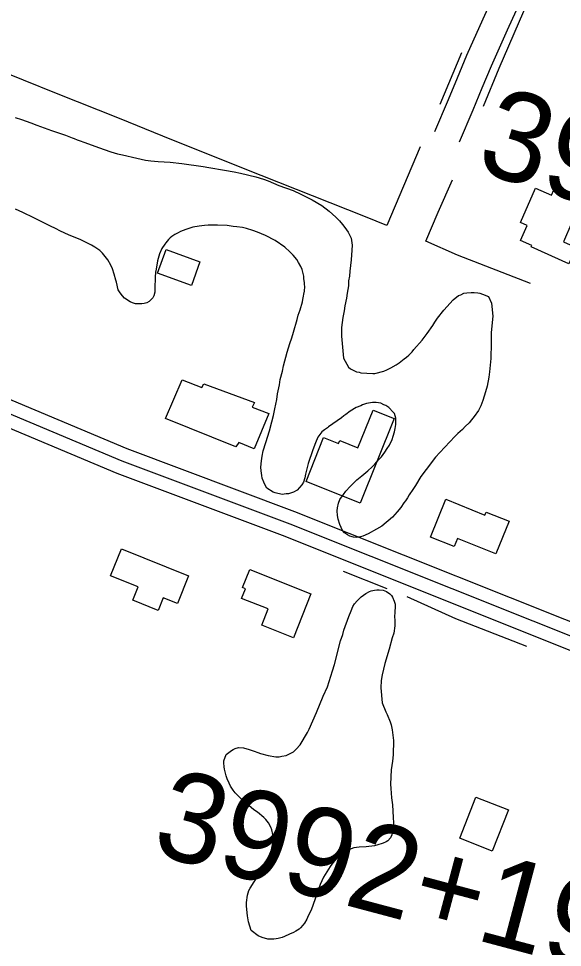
# Model space of a CAD drawing. Extents: x 3297735 to 3335592, y 670436 to 695807.
# Drawn here: x 3315202 to 3315811, y 691960 to 693000 of the extents above; entities that cross this region are included whole.
import ezdxf

# ---------------------------------------------------------------- set-up
doc = ezdxf.new("R2010")
doc.units = 0
for name, color, linetype in [('V-BLDG-OTLN', 7, 'Continuous'), ('V-BORW-LINE', 7, 'Continuous'), ('V-ROAD-CNTR', 7, 'Continuous'), ('V-SITE-VEGE', 7, 'Continuous'), ('V-SURV-IDEN', 7, 'Continuous'), ('V-TOPO-SHOR', 7, 'Continuous')]:
    doc.layers.add(name, color=color, linetype=linetype)

msp = doc.modelspace()

# ---------------------------------------------------------------- linework, layer by layer
at = {"layer": 'V-BLDG-OTLN'}
for points in [[(3315801.5, 692808), (3315857, 692783.3), (3315846.9, 692760.3), (3315821.9, 692771.4), (3315812.3, 692749.6), (3315826.5, 692743.3), (3315818.5, 692725.3), (3315776.3, 692744), (3315777, 692745.6), (3315764.3, 692751.3), (3315771.8, 692768.2), (3315764.1, 692771.6), (3315781, 692809.8), (3315798.8, 692801.9)], [(3315367.2, 692741.2), (3315405.2, 692727.5), (3315395.6, 692700.8), (3315357.5, 692714.6)], [(3315445.2, 692520.4), (3315366.4, 692552), (3315385.3, 692595.1), (3315407.4, 692586.8), (3315409.4, 692590.9), (3315466.1, 692570), (3315463.7, 692564.5), (3315482.4, 692557.7), (3315465.9, 692518), (3315448.6, 692525.2)], [(3315622.7, 692551.9), (3315584.7, 692457), (3315524, 692481.4), (3315543.7, 692530.5), (3315560.4, 692523.8), (3315561.8, 692527.4), (3315582.2, 692519.2), (3315599.1, 692561.3)], [(3315663.5, 692419.1), (3315680.5, 692461.5), (3315724.4, 692443.9), (3315725.7, 692447.2), (3315751.4, 692436.9), (3315736.7, 692400.3), (3315693.6, 692417.5), (3315690, 692408.5)], [(3315317.3, 692406.1), (3315392.5, 692375.8), (3315380, 692344.7), (3315364, 692351.1), (3315358.3, 692337.1), (3315329.8, 692348.6), (3315335.8, 692363.4), (3315305.1, 692375.8)], [(3315461, 692382.8), (3315529.4, 692355.7), (3315510, 692306.5), (3315474.4, 692320.6), (3315481.6, 692338.7), (3315451.8, 692350.5), (3315456.1, 692361.4), (3315453, 692362.6)], [(3315696.1, 692082), (3315714.3, 692128), (3315750.7, 692113.6), (3315732.5, 692067.6)]]:
    msp.add_lwpolyline(points, close=True, dxfattribs=at)
at = {"layer": 'V-BORW-LINE'}
msp.add_spline([(3316995.2, 691930.5), (3317005, 692007.7), (3317000.7, 692060.5), (3316979, 692099.5), (3316906.2, 692141.1), (3316833.3, 692187.2), (3316697.4, 692287.6), (3316663.3, 692310.2), (3316619.6, 692296.1), (3316590.9, 692259.4), (3316565, 692210.5), (3316480.2, 692005.7), (3316389.2, 691825.2), (3316305.5, 691699.3), (3316276.5, 691659.4), (3316186.6, 691545.7), (3316036.8, 691382.1), (3315921.1, 691241.4), (3315848.1, 691140), (3315652.3, 690837.6), (3315431.2, 690420.7), (3315366.5, 690281.6), (3315351.9, 690233.4), (3315347.6, 690183.5), (3315387.2, 690117.4), (3315426.1, 690095.1), (3315473.6, 690094.3), (3315510.7, 690108.4), (3315542.5, 690128.5), (3315605.1, 690188.3), (3315659, 690264.4), (3315681, 690299), (3315904.7, 690642.2), (3316008, 690811.4), (3316078, 690936.9), (3316101.2, 690968.5), (3316112.2, 690877.5), (3316165, 690879), (3316235.5, 690925.6), (3316271.1, 690958.6), (3316327.1, 691033.6), (3316466.8, 691261.1), (3316568, 691464.7), (3316598.4, 691502.4), (3316633.6, 691520.7), (3316678.1, 691524.6), (3316723.8, 691458.6), (3316763, 691470.8), (3316787.6, 691500), (3316883.3, 691688.4), (3316909.4, 691731.2), (3316973.6, 691855.6), (3316995.2, 691930.5)], degree=3, dxfattribs=at)
at = {"layer": 'V-ROAD-CNTR'}
for points in [[(3316195.1, 692158), (3315869, 692288.8), (3315506.1, 692433.7), (3315318.1, 692504.1), (3315015.5, 692631), (3314723.7, 692747.9), (3314551, 692817.4), (3314462.7, 692856.2), (3314264.4, 692935.5), (3314179.8, 692969.1), (3313993.7, 693034.9), (3313899.6, 693073.9), (3313699.7, 693161.3), (3313629.3, 693187.1), (3313422.5, 693270.4), (3313253.4, 693339.7)], [(3316189.5, 692144.1), (3315863.5, 692274.8), (3315500.7, 692419.7), (3315312.5, 692490.2), (3315009.8, 692617.1), (3314718.1, 692734), (3314545.2, 692803.6), (3314456.9, 692842.3), (3314258.9, 692921.6), (3314174.6, 692955.1), (3313988.4, 693020.9), (3313893.7, 693060.1), (3313694.1, 693147.4), (3313623.9, 693173.1), (3313416.8, 693256.5), (3313247.7, 693325.9)], [(3315781, 693136.9), (3315740.1, 693039.1), (3315722, 692999), (3315703.8, 692958.4), (3315693.2, 692933.2), (3315683.2, 692908.7), (3315668, 692873.1)], [(3315808.1, 693123.9), (3315767.6, 693027.2), (3315749.3, 692986.7), (3315731.3, 692946.5), (3315720.9, 692921.8), (3315710.9, 692897.1), (3315695.6, 692861.3)], [(3316200.7, 692171.9), (3315874.6, 692302.7), (3315511.5, 692447.6), (3315323.6, 692518.1), (3315021.2, 692644.9), (3314797.3, 692734.6)]]:
    msp.add_lwpolyline(points, dxfattribs=at)
at = {"layer": 'V-SITE-VEGE'}
for points in [[(3315198.1, 692889.1), (3315205.1, 692886.9), (3315215.6, 692883), (3315222.3, 692880.4)], [(3315222.3, 692880.4), (3315238.8, 692874.5), (3315254.4, 692869.2), (3315262.1, 692866.3), (3315264.2, 692865.3), (3315267.6, 692864.1), (3315270, 692863.4), (3315276.2, 692861), (3315291.5, 692855.4), (3315305.4, 692850.6), (3315312.8, 692848.4), (3315318.3, 692847.2), (3315334.6, 692843.3), (3315344.2, 692841.3), (3315350, 692840.3), (3315358.3, 692839.6), (3315371.8, 692838.8), (3315385, 692837.6), (3315408.7, 692834.1), (3315415.1, 692832.9), (3315432.6, 692830), (3315443.4, 692828), (3315450.6, 692826.6), (3315467.6, 692822.7), (3315476.2, 692820), (3315481.7, 692818.1), (3315493.7, 692813), (3315509.5, 692807.2), (3315518.1, 692803.3), (3315523.4, 692800.6), (3315530.8, 692796.8), (3315541.6, 692790.5), (3315549.9, 692784.2), (3315557.4, 692777.5), (3315561.4, 692773.4), (3315565, 692769.1), (3315567.4, 692766), (3315571.2, 692760.7), (3315574.5, 692754), (3315575.7, 692746), (3315575.4, 692740.5), (3315574.7, 692729.5), (3315573, 692716.8), (3315572.5, 692711.5), (3315571.7, 692706), (3315571.5, 692700.5), (3315570.2, 692692.4), (3315569.3, 692686.6), (3315567.5, 692678.2), (3315566.8, 692672.7), (3315565.1, 692665), (3315563.6, 692653.8), (3315563.8, 692644.2), (3315565.9, 692619.4), (3315571.7, 692609.3)], [(3315414.4, 692768.4), (3315410.4, 692768), (3315404.4, 692767.5), (3315397.2, 692766.1), (3315393.8, 692765.1), (3315389.2, 692763.5), (3315383.5, 692761.3), (3315380.6, 692759.9), (3315377.2, 692758), (3315373.6, 692755.6), (3315371.9, 692754.2), (3315370, 692752.3), (3315367.1, 692748.7), (3315365.7, 692747.3), (3315362.3, 692742.2), (3315359.7, 692736.5), (3315357.5, 692728.4), (3315356.2, 692719.3), (3315355.5, 692715.7), (3315355, 692710.4), (3315354.5, 692697.4), (3315354.5, 692693.6), (3315353.5, 692689.3), (3315352.5, 692687.1), (3315350.8, 692685.5), (3315348.2, 692683.1), (3315345.6, 692681.6), (3315342.7, 692680.7), (3315340, 692680.2), (3315336.2, 692680.2), (3315332.8, 692680.5), (3315329.5, 692681.5), (3315326.9, 692682.7), (3315320.6, 692686.8), (3315318.3, 692689.4), (3315315.9, 692692.5), (3315313.7, 692695.9), (3315311.6, 692704.8), (3315310.9, 692706.9), (3315309.2, 692713.4), (3315307.1, 692719.7), (3315305.2, 692723.7), (3315302.1, 692729.5), (3315296.1, 692737.2), (3315293, 692739.9), (3315287.5, 692743.7), (3315283.5, 692746.1), (3315271.7, 692751.9), (3315257.8, 692757.7), (3315249, 692761.8), (3315243.5, 692764.7), (3315237.7, 692767.4), (3315224.3, 692774.1), (3315219.1, 692776.6), (3315206.6, 692782.6), (3315198.7, 692786.2)], [(3315615, 692518.3), (3315617.4, 692522.1), (3315620.3, 692528.3), (3315621.7, 692532.1), (3315623.2, 692537.2), (3315623.9, 692540.8), (3315624.6, 692545.1), (3315624.7, 692552.3), (3315623, 692557.5), (3315621.6, 692559.2), (3315616.6, 692564.3), (3315613.2, 692566.7), (3315611.3, 692567.4), (3315607.7, 692569.1), (3315602.7, 692569.8), (3315598.4, 692569.9), (3315591.6, 692568.9), (3315587.1, 692567.3), (3315585.2, 692566.3), (3315580.1, 692564.2), (3315573.4, 692560.1), (3315568.6, 692556.5), (3315566.2, 692554.9), (3315563.8, 692552.7), (3315549, 692542.6), (3315547.9, 692541.6), (3315544.5, 692539.3), (3315541.6, 692536.9), (3315537.3, 692530.9), (3315534.6, 692524.7), (3315531.7, 692516.8), (3315526.4, 692501.7), (3315523.5, 692489.5), (3315522.8, 692485.6), (3315521.3, 692480.8), (3315519.4, 692477.5), (3315514.1, 692471.8), (3315510, 692469.4), (3315504.2, 692467.5), (3315501.6, 692467.5), (3315497.3, 692467), (3315489.4, 692468.7), (3315487.2, 692469.5), (3315480, 692474), (3315478.1, 692477.2), (3315476.7, 692480.5), (3315475, 692485.3), (3315474.3, 692488.2), (3315473.6, 692493.5), (3315473.4, 692497.6), (3315474.1, 692504.5), (3315474.9, 692509.8), (3315476.1, 692515.8), (3315478.8, 692525.1), (3315482.9, 692538), (3315485.8, 692548.3), (3315487.5, 692555.5), (3315489.2, 692562.9), (3315491.2, 692573.2), (3315492.2, 692579.7), (3315494.1, 692589.5), (3315495.1, 692595.8), (3315497.5, 692605.1), (3315498.7, 692611.1), (3315502.9, 692626.4), (3315505.8, 692635.8), (3315508.2, 692642.2), (3315509.9, 692648.7), (3315514, 692662.8), (3315515.2, 692667.6), (3315517.4, 692673.6), (3315519.9, 692682.5), (3315520.3, 692685.3), (3315521.3, 692688.9), (3315521.6, 692691.3), (3315522.1, 692694.4), (3315522.6, 692699.7), (3315522.3, 692701.9), (3315522.3, 692704.3), (3315521.6, 692708.4), (3315521.4, 692711.5), (3315520.9, 692714.3), (3315519.5, 692718.9), (3315518.3, 692722), (3315515.7, 692726.6), (3315513.6, 692730), (3315509.5, 692735), (3315505.9, 692738.6), (3315500.4, 692743.9), (3315489.4, 692751.1), (3315478.6, 692756.7), (3315469.5, 692760.6), (3315464.5, 692762.5), (3315457.3, 692764.7), (3315452.8, 692765.7), (3315446.6, 692766.4), (3315442.5, 692767.1), (3315435.5, 692767.9), (3315424.7, 692768.6), (3315420.4, 692768.6), (3315414.4, 692768.4)], [(3315571.7, 692609.3), (3315573.8, 692607.6), (3315576, 692606.4), (3315578.1, 692605.4), (3315580.7, 692604.4), (3315583.4, 692604), (3315585.5, 692603.2), (3315598.7, 692602.2), (3315601.1, 692602.5), (3315611.2, 692605.1), (3315614.6, 692606.5), (3315619.1, 692608.6), (3315624.9, 692612), (3315628.2, 692614.3), (3315634, 692618.9), (3315636.4, 692620.6), (3315639.1, 692622.7), (3315642.9, 692626.5), (3315644.8, 692629.2), (3315654, 692639.7), (3315659.8, 692647.3), (3315666, 692656.2), (3315668.2, 692659.8), (3315671.3, 692664.3), (3315678.3, 692673.1), (3315688.7, 692684.9), (3315694.9, 692689.6), (3315697.3, 692690.6), (3315700.9, 692692.2), (3315704, 692692.7), (3315709.1, 692693.2), (3315712.4, 692693.2), (3315716.5, 692692.7), (3315718.7, 692692.2), (3315721.8, 692691.2), (3315728.5, 692688.5), (3315731.8, 692681.1), (3315733.1, 692666.7), (3315731.5, 692648.3), (3315731.4, 692635.3), (3315731.2, 692631.2), (3315730.9, 692624.3), (3315730.9, 692619), (3315729.6, 692604.4), (3315728.9, 692598.2), (3315726.9, 692588.3), (3315725.2, 692581.9), (3315722.1, 692572.3), (3315719.7, 692566.3), (3315717, 692560.8), (3315712.2, 692554.1), (3315709.3, 692550.3), (3315706.6, 692547.2), (3315702.1, 692542.9), (3315699.2, 692539.8), (3315694.1, 692535.2), (3315690.5, 692531.7), (3315673.7, 692514), (3315669.1, 692508.7), (3315658.5, 692494.8), (3315652.7, 692487), (3315646.5, 692477.1), (3315643.6, 692472.4), (3315639.7, 692466.6), (3315637.8, 692463.3), (3315635.4, 692459.7), (3315633.7, 692457.5), (3315630.1, 692452.3), (3315626, 692447.3), (3315620.7, 692441.3), (3315608.9, 692431.5), (3315603.1, 692427.9), (3315593.5, 692422.7), (3315587.8, 692420.3), (3315584.9, 692419.3), (3315580.1, 692418.9), (3315577.2, 692419.1), (3315573.1, 692420.3), (3315570.5, 692421.6), (3315566.9, 692424), (3315564.8, 692426.6), (3315561.7, 692433.1), (3315560, 692439.1), (3315559.3, 692443.2), (3315558.9, 692448.5), (3315559.1, 692452), (3315560.3, 692457.3), (3315562, 692461.1), (3315565.9, 692466.9), (3315568.5, 692470.5), (3315573.6, 692476), (3315577.2, 692479.6), (3315581, 692483.1), (3315586.6, 692487.7), (3315593.3, 692493.4), (3315598.1, 692497.9), (3315601.2, 692501), (3315605.6, 692506.1), (3315608.5, 692509.2), (3315612.3, 692514.4), (3315615, 692518.3)], [(3315432.7, 692159.3), (3315432.3, 692162.1), (3315431.8, 692166.4), (3315431.8, 692168.8), (3315434.4, 692175.6), (3315440.4, 692180.3), (3315442.3, 692181.5), (3315444.7, 692182.5), (3315448.2, 692183.4), (3315453.9, 692183.1), (3315460.3, 692181.2), (3315466, 692179.3), (3315470, 692178.1), (3315473.1, 692176.9), (3315481.6, 692174.5), (3315490.1, 692173.3), (3315493.9, 692173.3), (3315497, 692173.7), (3315501.8, 692174.7), (3315504.8, 692176.1), (3315509.8, 692178.9), (3315512.9, 692181.8), (3315517.4, 692186.5), (3315525.6, 692200.4), (3315527.5, 692204), (3315535.8, 692222.9), (3315543.2, 692240.9), (3315548, 692251.6), (3315553.8, 692269.6), (3315555.7, 692276.4), (3315562.7, 692302.9), (3315565.1, 692310), (3315566.5, 692314.8), (3315572, 692330.4), (3315574.6, 692336.6), (3315576.5, 692341.5), (3315578.2, 692344.4), (3315581.3, 692347.9), (3315585.8, 692352.2), (3315590.8, 692355.9), (3315595.1, 692358.3), (3315597, 692359), (3315600.8, 692359.9), (3315603.4, 692360.2), (3315606, 692360.1), (3315610.3, 692359.7), (3315614.3, 692358.2), (3315617.8, 692355.8), (3315619.7, 692353.7), (3315620.9, 692352), (3315622.8, 692347.3), (3315623.7, 692344), (3315623.9, 692341.6), (3315623.5, 692335.2), (3315623.2, 692329.7), (3315623.4, 692326.2), (3315623.4, 692319.8), (3315622.2, 692311.5), (3315620.5, 692306.3), (3315617.1, 692293.7), (3315612.3, 692277.6), (3315610.7, 692271.2)], [(3315610.7, 692271.2), (3315609.2, 692265.1), (3315608.2, 692258.7), (3315607.7, 692250.2), (3315609.3, 692233.6), (3315613.3, 692223.4), (3315615, 692220.5), (3315618.3, 692212.4), (3315619.2, 692209.1), (3315620.6, 692203.4), (3315622, 692191.3), (3315621.7, 692175.2), (3315621, 692168.3), (3315619.5, 692158.4), (3315618.7, 692142.7), (3315619, 692137.5), (3315619.9, 692127.1), (3315620.8, 692119.5), (3315621.7, 692105.3), (3315621.9, 692099.1), (3315621.2, 692090.6), (3315620, 692085.8), (3315618.5, 692082.3), (3315615.7, 692079), (3315613.8, 692077.8), (3315610.4, 692076.4), (3315603.3, 692074.1), (3315600.5, 692073.4), (3315591.5, 692072.2), (3315583.4, 692071.8), (3315577.7, 692071.1), (3315574.4, 692070.1), (3315569.2, 692068), (3315566.3, 692066.1), (3315561.8, 692062.6), (3315558.5, 692059.8), (3315554, 692054.6), (3315551.1, 692050.3), (3315543.7, 692038.2), (3315539.9, 692030.2), (3315539.2, 692027.8), (3315536.1, 692019.8), (3315534.4, 692014.3), (3315529.6, 692001.5), (3315526.5, 691995.2), (3315524.8, 691991.4), (3315522.2, 691986.9), (3315520.5, 691984.5), (3315517.9, 691981.7), (3315516.2, 691980.3), (3315512.4, 691977.9), (3315509.8, 691976.5), (3315505.5, 691974.4), (3315499.9, 691971.8), (3315497.2, 691970.8), (3315492.7, 691969.7), (3315490.6, 691969.2), (3315488, 691969), (3315481.1, 691969), (3315475, 691970.7), (3315470.5, 691972.6), (3315462.7, 691978.8), (3315459.4, 691988.5), (3315458.9, 691992.8), (3315458.5, 691994.9), (3315458, 691998.5), (3315457.3, 692006.1), (3315457.3, 692009.9), (3315458.5, 692018.4), (3315460, 692023.4), (3315461.4, 692026), (3315473.1, 692044.4), (3315474.8, 692047.5), (3315477.4, 692051.3), (3315478.8, 692054.1), (3315481, 692057.9), (3315482.2, 692060.3), (3315483.8, 692064.5), (3315484.8, 692067.6), (3315486, 692072.6), (3315486.7, 692076.6), (3315487, 692082.3), (3315486.7, 692086.3), (3315485.6, 692091.5), (3315484.6, 692094.4), (3315481.8, 692099.4), (3315479, 692102.9), (3315476.6, 692105.3), (3315469.5, 692111), (3315465.5, 692113.9), (3315459.8, 692118.7), (3315454.9, 692122.5), (3315447.6, 692129.8), (3315444.7, 692132.9), (3315442.4, 692135.8), (3315439.5, 692140.3), (3315437.9, 692143.6), (3315435.8, 692148.6), (3315434.6, 692151.9), (3315433.9, 692155), (3315432.7, 692159.3)]]:
    msp.add_lwpolyline(points, dxfattribs=at)
at = {"layer": 'V-TOPO-SHOR'}
for p, q in [((3315698.3, 692961.3), (3315673.7, 692903.6)), ((3315614.8, 692361.2), (3315566, 692380.6))]:
    msp.add_line(p, q, dxfattribs=at)
for points in [[(3315722.9, 692901.8), (3315740.5, 692944.3), (3315768, 693007.9), (3315811, 693103.7)], [(3315652, 692856.3), (3315614.6, 692768.1), (3315590.6, 692777.8), (3315453.8, 692832), (3315363.5, 692868.1), (3315315, 692887.9), (3315244.3, 692916), (3315170.1, 692945.6), (3315136.5, 692958.5), (3315111.2, 692969.1)], [(3315775.3, 692703), (3315693.6, 692735), (3315658.1, 692750.4), (3315671.9, 692783), (3315688.2, 692819.3)], [(3315771.3, 692296.8), (3315691.8, 692327.8), (3315637.4, 692352.1)]]:
    msp.add_lwpolyline(points, dxfattribs=at)

# ---------------------------------------------------------------- texts
at = {"layer": 'V-SURV-IDEN'}
for s, rotation, p in [('3984+23.8', 343.0428, (3315711.9, 692830)), ('3992+19.1', 345.1097, (3315348.7, 692065.4))]:
    msp.add_text(s, height=100, rotation=rotation, dxfattribs=at).set_placement(p)

doc.saveas('drawing.dxf')
